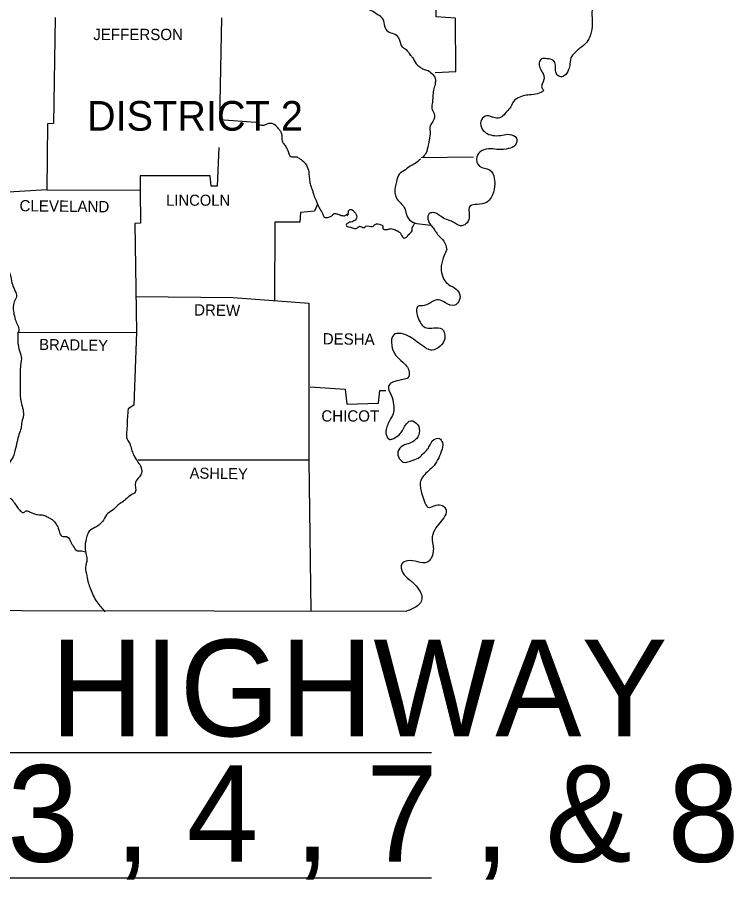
# Model space of a CAD drawing. Extents: x -35254 to 17396, y -8913 to 11592.
# Drawn here: x 14186 to 16857, y 3738 to 6952 of the extents above; entities that cross this region are included whole.
import ezdxf

# ---------------------------------------------------------------- set-up
doc = ezdxf.new("R2010")
doc.units = 0
for name, color, linetype in [('1', 7, 'Continuous'), ('2', 7, 'Continuous'), ('3', 7, 'Continuous')]:
    doc.layers.add(name, color=color, linetype=linetype)

msp = doc.modelspace()

# ---------------------------------------------------------------- linework, layer by layer
at = {"layer": '1'}
for p, q in [((15691.7, 6429.2), (15887.4, 6432.1)), ((11477.4, 4211.6), (15730.4, 4211.6)), ((11477.4, 3744.7), (15730.4, 3744.7))]:
    msp.add_line(p, q, dxfattribs=at)
for points in [[(15744.6, 6745.2), (15820.9, 6750.1), (15819.9, 6948.7), (15748.5, 6953.6), (15752.4, 7342), (15690.7, 7350.8), (15688.8, 7612.1), (16523.4, 7617.9)], [(14327.8, 6950.7), (14322, 6555.4), (14299.5, 6554.4), (14296.5, 6308.8)], [(14948.1, 6949.7), (14940.3, 6571), (15076.3, 6560.3)], [(14937.4, 6466.4), (14931.5, 6322.5), (14909, 6322.5), (14905.1, 6360.7), (14644.8, 6360.7), (14644.8, 6305.9)], [(14296.5, 6308.8), (14153.7, 6300)], [(14296.5, 6308.8), (14642.9, 6306.9)], [(14644.8, 6306.9), (14645.8, 6184.6), (14625.3, 6183.6), (14631.1, 5777.6)], [(15306.2, 6255), (15294.5, 6228.6), (15242.6, 6223.7), (15239.7, 6188.5), (15146.8, 6188.5), (15145.8, 5895.9)], [(15415.8, 6212), (15418.7, 6214.9), (15421.7, 6217.8), (15421.7, 6217.8)], [(14628.2, 5910.6), (14991.2, 5907.7), (15273, 5886.2)], [(15273, 5886.2), (15273, 5301.1), (15280.8, 4738.5)], [(14188.9, 5776.6), (14631.1, 5777.6)], [(14631.1, 5777.6), (14621.3, 5505.6), (14599.8, 5491.9)], [(15277.9, 5574.1), (15409, 5566.2), (15414.8, 5509.5), (15533.2, 5513.4), (15538.1, 5561.3), (15560.6, 5561.3)], [(12050.1, 5535.9), (12052.1, 4744.4), (15637.9, 4738.5)], [(14637, 5302.1), (15273, 5302.1)]]:
    msp.add_lwpolyline(points, dxfattribs=at)
for points in [[(16461.7, 7381.2), (16439.2, 7352.8), (16406, 7370.4), (16406, 7393.9), (16410.9, 7418.3), (16399.1, 7434), (16378.6, 7427.2), (16378.6, 7396.8), (16376.6, 7367.5), (16370.7, 7325.4), (16384.4, 7312.7), (16415.7, 7308.8), (16438.2, 7302.9), (16451.9, 7280.4), (16451, 7253), (16440.2, 7226.6), (16424.6, 7205.1), (16400.1, 7197.2), (16380.5, 7209.9), (16372.7, 7235.4), (16363.9, 7257.9), (16347.3, 7274.5), (16329.6, 7255.9), (16325.7, 7221.7), (16326.7, 7192.3), (16326.7, 7152.2), (16352.1, 7125.8), (16367.8, 7095.5), (16362.9, 7068.1), (16344.3, 7035.8), (16336.5, 7007.4), (16328.7, 6969.3), (16329.6, 6927.2), (16322.8, 6886.1), (16309.1, 6858.7), (16283.7, 6836.2), (16267, 6821.5), (16253.3, 6806.8), (16246.5, 6777.5), (16241.6, 6756.9), (16223, 6732.5), (16208.3, 6730.5), (16196.6, 6740.3), (16192.7, 6756.9), (16192.7, 6773.6), (16184.8, 6790.2), (16160.4, 6797.1), (16140.8, 6796.1), (16132, 6782.4), (16144.7, 6744.2), (16149.6, 6719.8), (16142.8, 6686.5), (16146.7, 6682.6), (16111.5, 6664), (16083.1, 6661.1), (16059.6, 6654.2), (16037.1, 6639.5), (16026.3, 6618), (16010.7, 6600.4), (15997, 6583.8), (15978.4, 6575.9), (15957.9, 6579.9), (15930.5, 6582.8), (15914.8, 6563.2), (15919.7, 6534.8), (15938.3, 6518.2), (15965.7, 6510.4), (15994.1, 6512.3), (16021.4, 6515.3), (16046.9, 6501.6), (16042, 6475.2), (16017.5, 6462.4), (15981.3, 6458.5), (15952, 6461.5), (15916.8, 6453.6), (15899.1, 6431.1), (15908.9, 6396.9), (15947.1, 6383.2), (15964.7, 6350.9), (15965.7, 6320.6), (15953, 6280.5), (15935.3, 6261.9), (15901.1, 6254), (15874.7, 6249.2), (15870.8, 6204.1), (15859, 6181.6), (15838.5, 6174.8), (15809.1, 6189.5), (15791.5, 6196.3), (15770, 6206.1), (15742.6, 6222.7), (15722.1, 6219.8), (15727.9, 6176.7), (15729.9, 6174.8), (15753.4, 6142.5), (15776.8, 6117.1), (15787.6, 6086.7)], [(15448.1, 7066.1), (15451, 7026), (15474.5, 7020.1), (15484.3, 7009.4), (15489.2, 6986.9), (15505.8, 6977.1), (15528.3, 6963.4), (15542, 6953.6), (15551.8, 6937.9), (15557.7, 6912.5), (15573.3, 6895.9), (15594.9, 6888.1), (15610.5, 6869.5), (15620.3, 6843), (15636, 6831.3), (15651.6, 6810.8), (15659.4, 6802), (15673.1, 6778.5), (15686.8, 6766.7), (15696.6, 6759.9), (15712.3, 6755), (15731.8, 6742.3), (15744.6, 6722.7), (15744.6, 6708), (15739.7, 6685.5), (15735.8, 6662), (15733.8, 6635.6), (15731.8, 6612.1), (15740.6, 6592.6), (15735.8, 6563.2), (15726, 6547.6), (15725, 6526), (15722.1, 6493.8), (15718.1, 6475.2), (15709.3, 6444.8), (15696.6, 6429.2)], [(15076.3, 6560.3), (15091, 6550.5), (15111.5, 6551.5), (15125.2, 6557.3), (15136, 6556.4), (15150.7, 6547.6), (15160.4, 6535.8), (15167.3, 6527), (15172.2, 6513.3), (15172.2, 6500.6), (15177.1, 6483), (15183, 6476.1), (15190.8, 6463.4), (15195.7, 6451.7), (15198.6, 6443.9), (15209.4, 6431.1), (15219.2, 6432.1), (15228, 6431.1), (15239.7, 6424.3), (15257.3, 6410.6), (15260.2, 6406.7), (15272, 6381.2), (15273.9, 6365.6), (15275.9, 6345), (15279.8, 6325.5), (15287.6, 6303.9), (15291.6, 6289.3), (15300.4, 6268.7), (15306.2, 6255), (15314.1, 6237.4), (15325.8, 6217.8), (15330.7, 6206.1), (15347.3, 6207.1), (15359.1, 6212), (15367.9, 6219.8), (15378.6, 6218.8), (15390.4, 6214.9), (15406, 6212), (15415.8, 6217.8), (15420.7, 6221.8), (15421.7, 6230.6), (15430.5, 6235.5), (15440.3, 6228.6), (15451, 6212.9), (15451, 6203.2), (15447.1, 6197.3), (15434.4, 6189.5), (15416.8, 6183.6), (15411.9, 6176.7), (15428.5, 6168.9), (15454.9, 6167), (15461.8, 6172.8), (15479.4, 6167.9), (15486.3, 6172.8), (15509.7, 6171.9), (15520.5, 6179.7), (15542, 6178.7), (15548.9, 6173.8), (15548.9, 6165), (15566.5, 6161.1), (15579.2, 6164), (15595.8, 6159.1), (15610.5, 6151.3), (15618.3, 6140.5), (15628.1, 6128.8), (15636.9, 6131.7), (15643.8, 6140.5), (15658.5, 6156.2), (15658.5, 6166), (15662.4, 6172.8), (15667.3, 6182.6)], [(15689.8, 6423.3), (15669.2, 6406.7), (15651.6, 6396.9), (15633, 6383.2), (15610.5, 6366.6), (15599.8, 6338.2), (15593.9, 6299), (15601.7, 6275.6), (15619.3, 6255), (15631.1, 6238.4), (15639.9, 6209), (15661.4, 6188.5), (15668.2, 6185.6)], [(14009.8, 6168.9), (14032.3, 6154.2), (14050.9, 6134.7), (14064.6, 6120), (14073.4, 6103.4), (14085.2, 6083.8), (14101.8, 6046.6), (14116.5, 6033.9), (14137, 6021.2), (14149.8, 6012.4), (14162.5, 5984), (14168.3, 5955.6), (14179.1, 5930.2), (14184, 5910.6), (14175.2, 5891.1), (14173.2, 5851.9), (14179.1, 5825.5), (14186.9, 5805.9), (14191.8, 5783.4), (14188.9, 5776.6)], [(15787.6, 6086.7), (15777.8, 6064.2), (15767.1, 6025.1), (15770, 5991.8), (15784.7, 5963.5), (15808.2, 5947.8), (15833.6, 5925.3), (15831.6, 5891.1), (15817, 5878.3), (15782.7, 5887.1), (15756.3, 5898.9), (15733.8, 5892), (15703.5, 5877.4), (15681, 5874.4), (15681.9, 5827.5), (15712.3, 5794.2), (15738.7, 5794.2), (15769, 5790.3), (15779.8, 5755.1), (15762.2, 5725.7), (15732.8, 5711), (15695.6, 5728.6), (15669.2, 5747.2), (15642.8, 5764.8), (15609.5, 5773.6), (15590.9, 5769.7), (15582.1, 5728.6), (15597.8, 5691.5), (15623.2, 5666), (15646.7, 5632.8), (15642.8, 5608.3), (15625.2, 5601.4), (15593.9, 5594.6), (15575.3, 5584.8), (15570.4, 5577), (15580.2, 5543.7), (15589, 5507.5), (15589, 5480.1), (15578.2, 5454.7), (15561.6, 5415.5), (15563.6, 5390.1), (15575.3, 5378.4), (15590, 5382.3), (15609.5, 5396), (15622.3, 5411.6), (15633, 5431.2), (15653.6, 5447.8), (15679, 5433.2), (15684.9, 5402.8), (15670.2, 5376.4), (15649.7, 5364.7), (15624.2, 5354.9), (15605.6, 5333.4), (15610.5, 5307.9), (15625.2, 5294.2), (15661.4, 5301.1), (15685.9, 5311.8), (15699.6, 5325.5), (15716.2, 5342.2), (15725, 5358.8), (15737.7, 5376.4), (15760.2, 5381.3), (15771, 5366.6), (15767.1, 5333.4), (15753.4, 5302.1), (15734.8, 5275.6), (15714.2, 5257), (15688.8, 5216.9), (15693.7, 5179.8), (15703.5, 5149.4), (15717.2, 5125.9), (15740.6, 5130.8), (15767.1, 5133.8), (15782.7, 5121), (15780.8, 5093.7), (15761.2, 5067.2), (15742.6, 5041.8), (15732.8, 5006.6), (15736.7, 4982.1), (15736.7, 4959.6), (15728.9, 4935.2), (15715.2, 4921.5), (15679, 4922.4), (15640.8, 4926.3), (15620.3, 4914.6), (15624.2, 4881.3), (15646.7, 4856.9), (15662.4, 4844.2), (15684.9, 4816.8), (15694.7, 4794.3), (15691.7, 4774.7), (15678, 4758.1), (15637.9, 4738.5)], [(14188.9, 5776.6), (14192.8, 5715.9), (14201.6, 5686.6), (14198.7, 5655.3), (14197.7, 5624.9), (14197.7, 5597.5), (14197.7, 5571.1), (14197.7, 5543.7), (14199.7, 5524.2), (14206.5, 5495.8), (14209.4, 5469.4), (14203.6, 5443.9), (14200.6, 5420.4), (14192.8, 5397), (14186, 5370.5), (14178.1, 5336.3), (14171.3, 5313.8), (14157.6, 5290.3), (14148.8, 5268.8), (14135.1, 5255.1), (14133.1, 5231.6), (14136.1, 5210.1), (14134.1, 5190.5), (14140.9, 5171.9), (14158.6, 5159.2)], [(14599.8, 5491.9), (14596.9, 5461.5), (14595.9, 5433.2), (14594, 5405.8), (14594, 5385.2), (14605.7, 5362.7), (14612.5, 5341.2), (14619.4, 5322.6), (14633.1, 5298.1), (14645.8, 5279.5), (14649.7, 5253.1), (14641.9, 5239.4), (14627.2, 5218.9), (14626.2, 5181.7), (14608.6, 5170), (14586.1, 5150.4), (14573.4, 5141.6), (14559.7, 5132.8), (14545, 5117.1), (14523.5, 5102.5), (14507.9, 5078), (14490.2, 5059.4), (14475.6, 5049.6), (14455, 5036.9), (14446.2, 5017.3), (14439.4, 4981.1), (14442.3, 4954.7), (14446.2, 4931.2), (14441.3, 4901.9), (14446.2, 4869.6), (14451.1, 4844.2), (14458.9, 4821.7), (14469.7, 4796.2), (14483.4, 4772.7), (14512.7, 4736.5)], [(13624.4, 5265.9), (13640, 5276.6), (13654.7, 5282.5), (13669.4, 5279.5), (13685, 5277.6), (13698.7, 5279.5), (13716.3, 5276.6), (13731, 5267.8), (13747.6, 5261), (13764.3, 5261), (13778.9, 5261), (13791.7, 5252.2), (13815.1, 5253.1), (13834.7, 5261), (13854.3, 5266.8), (13880.7, 5269.8), (13904.2, 5253.1), (13920.8, 5239.4), (13934.5, 5223.8), (13944.3, 5206.2), (13955.1, 5196.4), (13972.7, 5189.5), (13986.4, 5186.6), (14003, 5181.7), (14011.8, 5177.8), (14019.6, 5159.2), (14032.3, 5133.8), (14056.8, 5125), (14087.1, 5136.7), (14111.6, 5143.6), (14129.2, 5149.4), (14140, 5153.3), (14149.8, 5154.3), (14146.8, 5156.3), (14158.6, 5159.2), (14169.3, 5151.4), (14176.2, 5140.6), (14187.9, 5125), (14198.7, 5111.3), (14209.4, 5106.4), (14220.2, 5112.2), (14234.9, 5107.4), (14247.6, 5102.5), (14262.3, 5098.5), (14275, 5097.6), (14291.6, 5093.7), (14304.3, 5086.8), (14316.1, 5080), (14327.8, 5067.2), (14339.6, 5047.7), (14343.5, 5032), (14357.2, 5016.4), (14369.9, 5016.4), (14388.5, 4990.9), (14395.3, 4981.1), (14410, 4963.5), (14420.8, 4963.5), (14441.3, 4959.6)]]:
    msp.add_spline(points, degree=3, dxfattribs=at)
at = {"layer": '3'}
msp.add_line((15665.3, 6184.6), (15726.9, 6176.7), dxfattribs=at)

# ---------------------------------------------------------------- texts
at = {"layer": '2'}
for s, height, p in [('JEFFERSON', 42.07, (14469.7, 6866.5)), ('LINCOLN', 41.09, (14741.7, 6249.2)), ('CHICOT', 42.07, (15319.9, 5444.9)), ('ARKANSAS HIGHWAY', 360, (11554.8, 4272.5)), ('DISTRICTS 3 , 4 , 7 , & 8', 360, (11474, 3804.5))]:
    msp.add_text(s, height=height, dxfattribs=at).set_placement(p)
for s, height, rotation, p in [('CLEVELAND', 42.07, 359.3377, (14194.8, 6228.6)), ('DREW', 42.06, 359.2258, (14845.4, 5840.2)), ('DESHA', 42.06, 359.3704, (15324.8, 5732.6)), ('BRADLEY', 41.08, 359.1449, (14268.1, 5712)), ('ASHLEY', 41.09, 359.2361, (14828.8, 5232.6))]:
    msp.add_text(s, height=height, rotation=rotation, dxfattribs=at).set_placement(p)
at = {"layer": '3'}
msp.add_text('DISTRICT 2', height=110.56, dxfattribs=at).set_placement((14446.2, 6529))

doc.saveas('drawing.dxf')
